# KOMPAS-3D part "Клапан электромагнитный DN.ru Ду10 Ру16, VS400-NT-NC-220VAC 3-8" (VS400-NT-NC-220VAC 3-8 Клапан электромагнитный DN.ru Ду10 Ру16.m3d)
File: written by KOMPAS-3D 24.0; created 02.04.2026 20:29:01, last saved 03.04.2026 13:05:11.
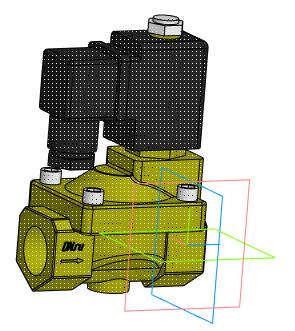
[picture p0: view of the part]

Document properties: Автор: artio; Полное имя файла: C:\Users\artio\OneDrive\Рабочий стол\Клапан электромагнитный DN.ru VS4x-xT-NC-x\VS400-NT-NC\VS400-NT-NC-220VAC 3-8 Клапан электромагнитный DN.ru Ду10 Ру16.m3d

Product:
- Body: Тело 1  | qty 1
    Масса: 1.030062
- Part/product: Клапан электромагнитный DN.ru Ду10 Ру16  | designation VS400-NT-NC-220VAC 3-8
    Масса: 0.797
    Раздел спецификации: Прочие изделия
    Примечание: D130-04660
    additional columns: ef56311e-7521-43dc-8291-0e6108b3d81d; VS400-ET-NC-220VAC 3-8; artio; c; Шероховатость не задана; Да

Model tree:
1. Операция без истории:1

Expressions: VS400-NT-NC-220VAC 3-8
